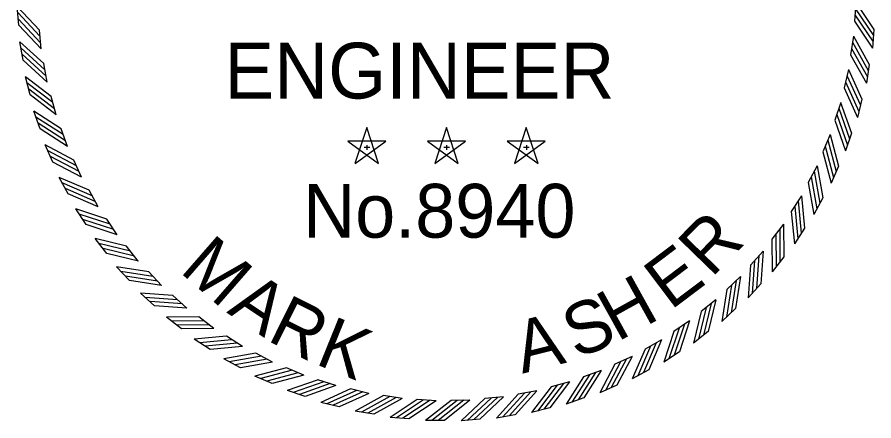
# Model space of a CAD drawing. Extents: x 1370130 to 1380143, y 377636 to 380256.
# Drawn here: x 1379550.7 to 1379756.8, y 377741.7 to 377838.9 of the extents above; entities that cross this region are included whole.
import ezdxf

# ---------------------------------------------------------------- set-up
doc = ezdxf.new("R2010")
doc.units = 0
doc.layers.add('STAMP_JUSTIN', color=7, linetype='Continuous')

msp = doc.modelspace()

# ---------------------------------------------------------------- linework, layer by layer
at = {"layer": 'STAMP_JUSTIN'}
for p, q in [((1379752.45, 377842.41), (1379752.12, 377837.89)), ((1379551.15, 377836.95), (1379550.73, 377841.45)), ((1379556.51, 377831.24), (1379556.09, 377835.76)), ((1379751.9, 377834.29), (1379751.2, 377829.81)), ((1379756.8, 377835.9), (1379756.47, 377831.39)), ((1379552.16, 377828.48), (1379551.38, 377832.94)), ((1379557.97, 377823.24), (1379557.19, 377827.7)), ((1379750.69, 377826.24), (1379749.62, 377821.84)), ((1379755.7, 377827.44), (1379755, 377822.97)), ((1379553.87, 377820.13), (1379552.72, 377824.5)), ((1379560.09, 377815.38), (1379558.94, 377819.77)), ((1379748.82, 377818.32), (1379747.38, 377814.02)), ((1379753.91, 377819.11), (1379752.84, 377814.71)), ((1379556.26, 377811.94), (1379554.75, 377816.21)), ((1379562.86, 377807.73), (1379561.35, 377812)), ((1379634.82, 377812.31), (1379631.99, 377803.62)), ((1379637.64, 377803.63), (1379634.83, 377812.32)), ((1379654.01, 377812.31), (1379651.18, 377803.62)), ((1379656.83, 377803.63), (1379654.01, 377812.32)), ((1379673.2, 377812.31), (1379670.37, 377803.62)), ((1379676.02, 377803.63), (1379673.2, 377812.32)), ((1379746.29, 377810.59), (1379744.51, 377806.42)), ((1379751.43, 377810.95), (1379750, 377806.65)), ((1379559.32, 377803.98), (1379557.46, 377808.11)), ((1379639.38, 377808.99), (1379630.25, 377809)), ((1379630.26, 377808.99), (1379637.64, 377803.62)), ((1379632, 377803.63), (1379639.39, 377808.99)), ((1379634.17, 377807.53), (1379635.53, 377807.53)), ((1379634.83, 377808.02), (1379634.83, 377806.88)), ((1379658.57, 377808.99), (1379649.44, 377809)), ((1379649.45, 377808.99), (1379656.83, 377803.62)), ((1379651.19, 377803.63), (1379658.58, 377808.99)), ((1379653.36, 377807.53), (1379654.72, 377807.53)), ((1379654.02, 377808.02), (1379654.02, 377806.88)), ((1379677.76, 377808.99), (1379668.63, 377809)), ((1379668.63, 377808.99), (1379676.02, 377803.62)), ((1379670.38, 377803.63), (1379677.77, 377808.99)), ((1379672.55, 377807.53), (1379673.9, 377807.53)), ((1379673.21, 377808.02), (1379673.21, 377806.88)), ((1379566.24, 377800.33), (1379564.38, 377804.46)), ((1379743.14, 377803.08), (1379741.02, 377799.08)), ((1379748.29, 377803.02), (1379746.51, 377798.86)), ((1379563.03, 377796.3), (1379560.84, 377800.26)), ((1379570.23, 377793.23), (1379568.03, 377797.2)), ((1379739.38, 377795.87), (1379736.93, 377792.05)), ((1379744.51, 377795.38), (1379742.39, 377791.38)), ((1379567.35, 377788.95), (1379564.84, 377792.72)), ((1379574.78, 377786.49), (1379572.27, 377790.26)), ((1379735.03, 377788.98), (1379732.28, 377785.38)), ((1379740.1, 377788.07), (1379737.67, 377784.26)), ((1379572.27, 377781.99), (1379569.46, 377785.53)), ((1379579.88, 377780.14), (1379577.06, 377783.7)), ((1379730.14, 377782.49), (1379727.1, 377779.12)), ((1379735.11, 377781.16), (1379732.37, 377777.56)), ((1379577.75, 377775.45), (1379574.66, 377778.75)), ((1379585.49, 377774.24), (1379582.38, 377777.55)), ((1379724.72, 377776.41), (1379721.41, 377773.31)), ((1379729.57, 377774.68), (1379726.54, 377771.32)), ((1379583.75, 377769.39), (1379580.39, 377772.43)), ((1379591.56, 377768.82), (1379588.19, 377771.86)), ((1379718.82, 377770.81), (1379715.27, 377767.99)), ((1379723.51, 377768.68), (1379720.21, 377765.58)), ((1379590.23, 377763.85), (1379586.63, 377766.59)), ((1379598.06, 377763.93), (1379594.45, 377766.68)), ((1379712.48, 377765.71), (1379708.7, 377763.2)), ((1379716.97, 377763.2), (1379713.43, 377760.39)), ((1379597.14, 377758.86), (1379593.33, 377761.3)), ((1379604.94, 377759.58), (1379601.12, 377762.03)), ((1379705.73, 377761.15), (1379701.76, 377758.96)), ((1379612.16, 377755.82), (1379608.15, 377757.94)), ((1379710.01, 377758.28), (1379706.24, 377755.77)), ((1379604.45, 377754.45), (1379600.45, 377756.57)), ((1379698.64, 377757.17), (1379694.5, 377755.31)), ((1379619.66, 377752.67), (1379615.49, 377754.45)), ((1379702.66, 377753.95), (1379698.7, 377751.76)), ((1379612.09, 377750.67), (1379607.93, 377752.45)), ((1379691.24, 377753.78), (1379686.96, 377752.27)), ((1379627.4, 377750.15), (1379623.09, 377751.58)), ((1379683.58, 377751.02), (1379679.2, 377749.87)), ((1379694.98, 377750.25), (1379690.85, 377748.39)), ((1379620.02, 377747.53), (1379615.73, 377748.96)), ((1379635.32, 377748.27), (1379630.91, 377749.34)), ((1379643.36, 377747.06), (1379638.88, 377747.76)), ((1379675.72, 377748.9), (1379671.26, 377748.11)), ((1379628.18, 377745.05), (1379623.78, 377746.12)), ((1379651.48, 377746.51), (1379646.96, 377746.84)), ((1379659.62, 377746.64), (1379655.09, 377746.6)), ((1379667.72, 377747.44), (1379663.2, 377747.02)), ((1379687.02, 377747.19), (1379682.76, 377745.68)), ((1379636.52, 377743.26), (1379632.05, 377743.97)), ((1379678.83, 377744.8), (1379674.46, 377743.65)), ((1379644.97, 377742.16), (1379640.46, 377742.5)), ((1379653.49, 377741.77), (1379648.97, 377741.73)), ((1379662.01, 377742.08), (1379657.51, 377741.66)), ((1379670.48, 377743.09), (1379666.02, 377742.3))]:
    msp.add_line(p, q, dxfattribs=at)
for points in [[(1379752.45, 377842.42), (1379756.79, 377835.91)], [(1379556.09, 377835.75), (1379550.73, 377841.46)], [(1379752.33, 377840.96), (1379756.67, 377834.46)], [(1379556.22, 377834.25), (1379550.86, 377839.96)], [(1379556.39, 377832.69), (1379551.03, 377838.39)], [(1379752.24, 377839.39), (1379756.59, 377832.89)], [(1379556.51, 377831.24), (1379551.15, 377836.94)], [(1379752.12, 377837.89), (1379756.47, 377831.38)], [(1379751.9, 377834.3), (1379755.7, 377827.45)], [(1379557.18, 377827.7), (1379551.37, 377832.94)], [(1379751.66, 377832.86), (1379755.46, 377826.01)], [(1379557.43, 377826.21), (1379551.62, 377831.45)], [(1379751.45, 377831.3), (1379755.25, 377824.46)], [(1379557.74, 377824.67), (1379551.93, 377829.91)], [(1379557.98, 377823.23), (1379552.17, 377828.48)], [(1379751.2, 377829.82), (1379755, 377822.97)], [(1379750.69, 377826.25), (1379753.9, 377819.11)], [(1379558.94, 377819.76), (1379552.71, 377824.5)], [(1379750.33, 377824.84), (1379753.55, 377817.7)], [(1379559.31, 377818.3), (1379553.08, 377823.04)], [(1379749.62, 377821.84), (1379752.84, 377814.71)], [(1379749.99, 377823.3), (1379753.21, 377816.17)], [(1379559.74, 377816.79), (1379553.52, 377821.53)], [(1379560.1, 377815.38), (1379553.87, 377820.12)], [(1379748.81, 377818.33), (1379751.43, 377810.95)], [(1379561.34, 377811.99), (1379554.75, 377816.21)], [(1379748.34, 377816.95), (1379750.96, 377809.58)], [(1379561.83, 377810.57), (1379555.24, 377814.78)], [(1379747.39, 377814.03), (1379750, 377806.65)], [(1379747.88, 377815.45), (1379750.49, 377808.07)], [(1379562.39, 377809.1), (1379555.79, 377813.31)], [(1379562.86, 377807.72), (1379556.27, 377811.94)], [(1379746.29, 377810.59), (1379748.29, 377803.02)], [(1379564.38, 377804.45), (1379557.46, 377808.11)], [(1379745.12, 377807.8), (1379747.12, 377800.23)], [(1379745.71, 377809.26), (1379747.71, 377801.69)], [(1379564.99, 377803.07), (1379558.07, 377806.73)], [(1379565.66, 377801.66), (1379558.74, 377805.31)], [(1379744.51, 377806.42), (1379746.51, 377798.85)], [(1379566.25, 377800.32), (1379559.33, 377803.98)], [(1379742.45, 377801.81), (1379743.81, 377794.1)], [(1379743.14, 377803.09), (1379744.51, 377795.38)], [(1379568.03, 377797.19), (1379560.83, 377800.26)], [(1379741.74, 377800.4), (1379743.11, 377792.7)], [(1379568.75, 377795.87), (1379561.55, 377798.94)], [(1379569.54, 377794.51), (1379562.34, 377797.58)], [(1379741.02, 377799.08), (1379742.39, 377791.37)], [(1379570.23, 377793.23), (1379563.03, 377796.3)], [(1379739.38, 377795.87), (1379740.1, 377788.08)], [(1379737.76, 377793.31), (1379738.49, 377785.52)], [(1379738.58, 377794.65), (1379739.31, 377786.86)], [(1379572.27, 377790.25), (1379564.84, 377792.72)], [(1379573.09, 377788.99), (1379565.66, 377791.46)], [(1379736.94, 377792.05), (1379737.67, 377784.26)], [(1379573.99, 377787.7), (1379566.56, 377790.17)], [(1379574.79, 377786.48), (1379567.36, 377788.95)], [(1379735.03, 377788.99), (1379735.11, 377781.16)], [(1379734.14, 377787.84), (1379734.22, 377780.02)], [(1379577.06, 377783.69), (1379569.46, 377785.53)], [(1379732.29, 377785.38), (1379732.37, 377777.56)], [(1379733.21, 377786.57), (1379733.29, 377778.75)], [(1379577.99, 377782.5), (1379570.38, 377784.34)], [(1379578.99, 377781.29), (1379571.39, 377783.13)], [(1379579.89, 377780.14), (1379572.28, 377781.99)], [(1379729.15, 377781.42), (1379728.58, 377773.61)], [(1379730.14, 377782.49), (1379729.57, 377774.69)], [(1379582.39, 377777.54), (1379574.65, 377778.75)], [(1379727.1, 377779.12), (1379726.54, 377771.32)], [(1379728.12, 377780.23), (1379727.56, 377772.43)], [(1379583.41, 377776.43), (1379575.67, 377777.64)], [(1379584.51, 377775.31), (1379576.77, 377776.52)], [(1379585.49, 377774.24), (1379577.76, 377775.45)], [(1379723.65, 377775.43), (1379722.44, 377767.7)], [(1379724.72, 377776.42), (1379723.51, 377768.69)], [(1379588.2, 377771.86), (1379580.39, 377772.43)], [(1379721.42, 377773.31), (1379720.21, 377765.58)], [(1379722.53, 377774.33), (1379721.32, 377766.6)], [(1379589.3, 377770.84), (1379581.5, 377771.4)], [(1379590.49, 377769.81), (1379582.69, 377770.38)], [(1379718.82, 377770.82), (1379716.98, 377763.21)], [(1379591.57, 377768.82), (1379583.76, 377769.39)], [(1379716.46, 377768.92), (1379714.62, 377761.31)], [(1379717.67, 377769.92), (1379715.83, 377762.31)], [(1379594.46, 377766.67), (1379586.63, 377766.59)], [(1379715.27, 377767.99), (1379713.43, 377760.38)], [(1379595.65, 377765.75), (1379587.82, 377765.67)], [(1379596.92, 377764.82), (1379589.09, 377764.74)], [(1379711.26, 377764.92), (1379708.79, 377757.49)], [(1379712.48, 377765.72), (1379710.01, 377758.29)], [(1379598.06, 377763.93), (1379590.24, 377763.85)], [(1379708.71, 377763.2), (1379706.24, 377755.77)], [(1379709.97, 377764.02), (1379707.5, 377756.59)], [(1379601.12, 377762.02), (1379593.33, 377761.3)], [(1379602.38, 377761.2), (1379594.59, 377760.47)], [(1379603.73, 377760.38), (1379595.93, 377759.65)], [(1379704.45, 377760.47), (1379701.38, 377753.27)], [(1379705.74, 377761.16), (1379702.66, 377753.96)], [(1379604.95, 377759.58), (1379597.15, 377758.86)], [(1379608.15, 377757.94), (1379600.44, 377756.57)], [(1379701.77, 377758.96), (1379698.7, 377751.76)], [(1379703.1, 377759.68), (1379700.03, 377752.48)], [(1379609.48, 377757.22), (1379601.77, 377755.85)], [(1379610.88, 377756.52), (1379603.17, 377755.15)], [(1379695.89, 377755.91), (1379692.23, 377748.99)], [(1379697.31, 377756.59), (1379693.65, 377749.67)], [(1379698.64, 377757.18), (1379694.98, 377750.25)], [(1379612.16, 377755.82), (1379604.46, 377754.46)], [(1379615.49, 377754.45), (1379607.93, 377752.45)], [(1379616.87, 377753.84), (1379609.31, 377751.84)], [(1379691.24, 377753.79), (1379687.02, 377747.19)], [(1379694.51, 377755.31), (1379690.85, 377748.39)], [(1379618.33, 377753.26), (1379610.76, 377751.26)], [(1379619.67, 377752.67), (1379612.1, 377750.67)], [(1379686.97, 377752.27), (1379682.75, 377745.68)], [(1379688.39, 377752.76), (1379684.18, 377746.16)], [(1379689.86, 377753.32), (1379685.65, 377746.72)], [(1379623.1, 377751.57), (1379615.72, 377748.96)], [(1379624.52, 377751.08), (1379617.15, 377748.47)], [(1379626.03, 377750.62), (1379618.65, 377748)], [(1379627.4, 377750.15), (1379620.03, 377747.53)], [(1379679.2, 377749.87), (1379674.46, 377743.64)], [(1379680.66, 377750.24), (1379675.92, 377744.01)], [(1379682.17, 377750.67), (1379677.43, 377744.44)], [(1379683.58, 377751.03), (1379678.84, 377744.8)], [(1379630.91, 377749.34), (1379623.78, 377746.12)], [(1379632.38, 377748.97), (1379625.24, 377745.75)], [(1379633.91, 377748.63), (1379626.77, 377745.41)], [(1379635.32, 377748.27), (1379628.19, 377745.06)], [(1379638.89, 377747.76), (1379632.04, 377743.96)], [(1379671.26, 377748.11), (1379666.02, 377742.3)], [(1379672.75, 377748.36), (1379667.51, 377742.55)], [(1379674.29, 377748.67), (1379669.05, 377742.85)], [(1379675.73, 377748.91), (1379670.49, 377743.09)], [(1379640.37, 377747.51), (1379633.53, 377743.72)], [(1379641.93, 377747.3), (1379635.09, 377743.51)], [(1379643.37, 377747.06), (1379636.52, 377743.27)], [(1379646.97, 377746.84), (1379640.46, 377742.49)], [(1379648.47, 377746.72), (1379641.96, 377742.37)], [(1379650.04, 377746.64), (1379643.53, 377742.29)], [(1379651.49, 377746.52), (1379644.98, 377742.17)], [(1379655.09, 377746.59), (1379648.96, 377741.72)], [(1379656.6, 377746.59), (1379650.47, 377741.72)], [(1379658.17, 377746.64), (1379652.04, 377741.77)], [(1379659.62, 377746.64), (1379653.5, 377741.77)], [(1379663.21, 377747.02), (1379657.5, 377741.66)], [(1379664.71, 377747.14), (1379659.01, 377741.78)], [(1379666.27, 377747.32), (1379660.57, 377741.96)], [(1379667.72, 377747.44), (1379662.02, 377742.08)]]:
    msp.add_lwpolyline(points, dxfattribs=at)

# ---------------------------------------------------------------- texts
for s, height, p in [('ENGINEER', 13.432, (1379600.58, 377819.27)), ('No.8940', 12.953, (1379619.53, 377785.77))]:
    msp.add_text(s, height=height, dxfattribs=at).set_placement(p)
for s, rotation, p in [('R', 45.7825, (1379717.72, 377775.9)), ('M', 318.9599, (1379589.58, 377777.64)), ('E', 37.0272, (1379707.9, 377768.15)), ('H', 29.0016, (1379695.1, 377760.57)), ('A', 326.256, (1379600.98, 377767.78)), ('R', 333.552, (1379610.53, 377761.14)), ('S', 21.7056, (1379685.16, 377756.53)), ('K', 337.9296, (1379622.12, 377755.46)), ('A', 14.0448, (1379672.24, 377753.01))]:
    msp.add_text(s, height=12.5, rotation=rotation, dxfattribs=at).set_placement(p)

doc.saveas('drawing.dxf')
